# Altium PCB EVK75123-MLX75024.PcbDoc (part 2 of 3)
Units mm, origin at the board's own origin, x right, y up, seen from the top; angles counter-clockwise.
Board outline 80 x 50 mm, 8 copper layers (Top Layer, GND_T, Signal Layer 1, Vcc1, Vcc2, Signal Layer 2, GND_B, Bottom Layer), stack 1.548 mm thick; 222 components, 135 nets, 746 pads, 778 vias.
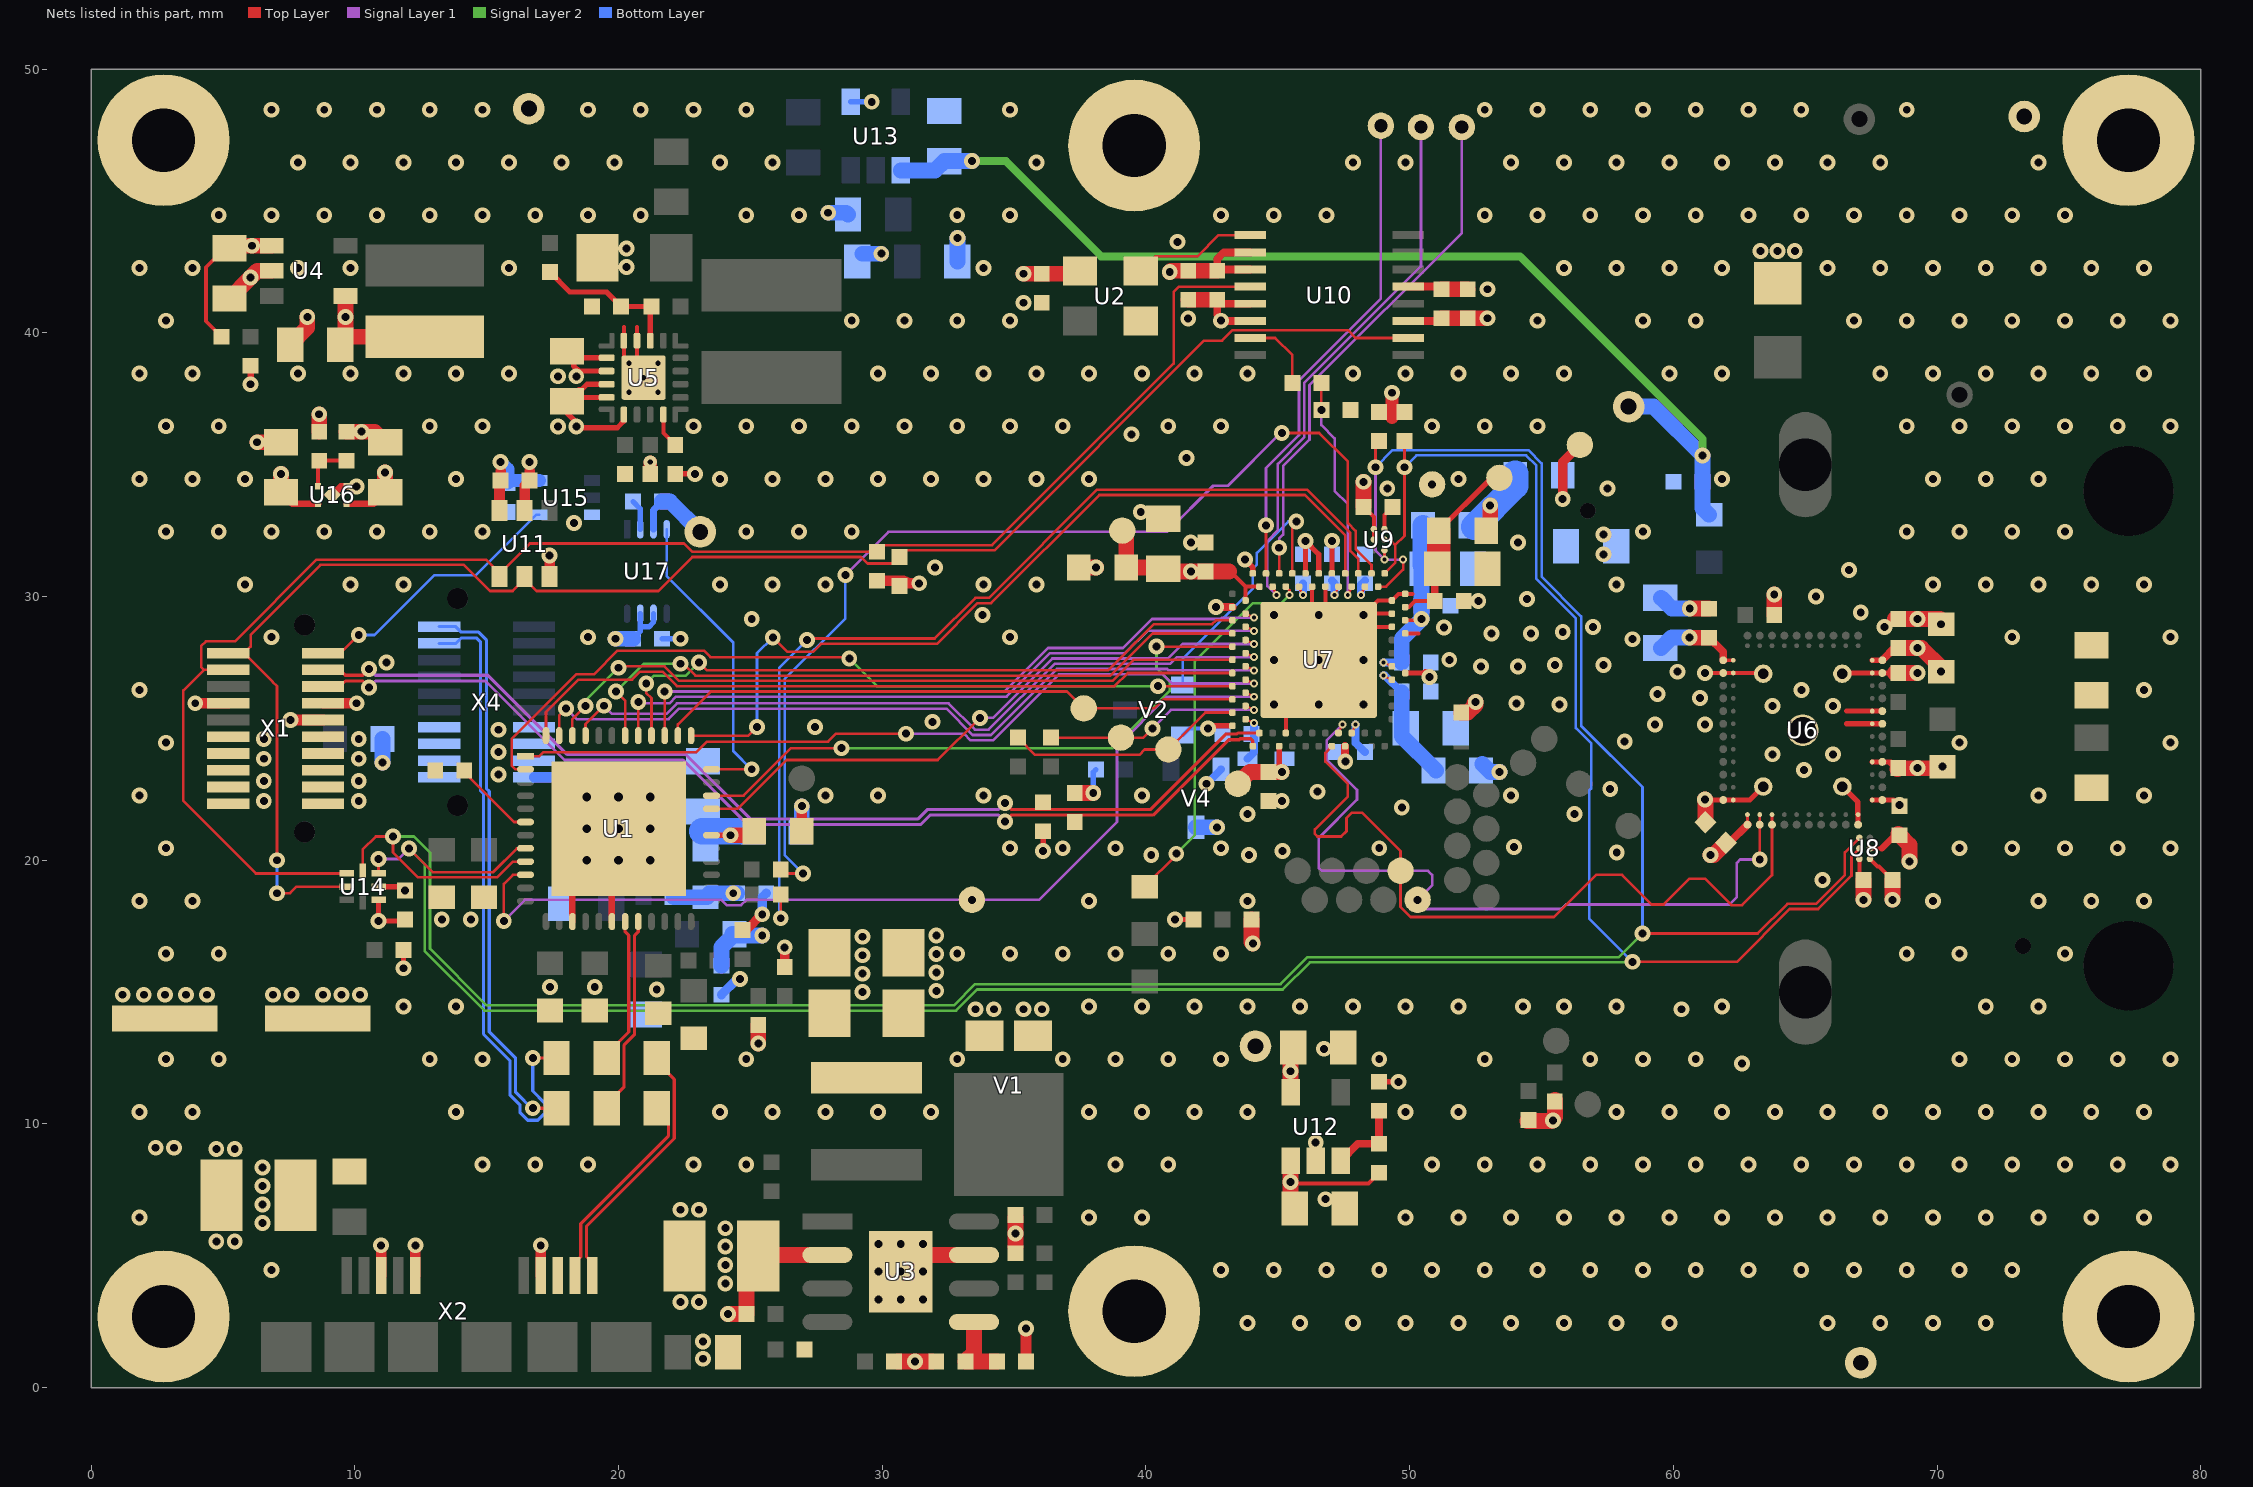
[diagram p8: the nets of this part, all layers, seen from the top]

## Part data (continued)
U10: library part ab1d2fae-9ac6-4ea7-8deb-ee514b9f58bf, "Serial programmable clock generator", Manufacturer=Cypress, Supplier Part Number 1=428-2177-5-ND
U11: library part CE87B2AE-2F79-437B-9DBA-CA9484908A67, "12-Bit Digital-to-Analog Converter with EEPROM Memory", Manufacturer=Microchip, Supplier Part Number 1=MCP4725A2T-E/CHCT-ND
U12: library part 000e727f-cc4e-40e8-9f49-f72307949e4f, "3.3V Fixed, 150 mA, Low Quiescent Current, CMOS Linear Regulator", Manufacturer="Analog Devices", Supplier Part Number 1=2074869
U13: library part 4dc81be8-c4c1-4461-86d3-06e5047a3865, "Switched-Capacitor Voltage Inverters", Manufacturer="TEXAS INSTRUMENTS", Supplier Part Number 1=595-TPS60400QDBVRQ1
U14: library part c6ef2881-e2fc-40f5-a959-5641457b75ea, "DUAL BIDIRECTIONAL I2C BUS AND SMBus VOLTAGE-LEVEL TRANSLATOR", Manufacturer="ON Semiconductor", Supplier Part Number 1=863-PCA9306AMUTCG
U15: library part FD5746C1-CD80-4158-946D-D65AE2EC754E, "74LVC1G17", Manufacturer="Texas Instruments", Supplier Part Number 1=1287609
U16: library part 41ab4844-91b0-416b-8011-5a243bc6cd3e, "1.8V LDO Regulator", Manufacturer=Micrel, Supplier Part Number 1=998-MIC5504-1.8YMTTZ
U17: library part 10037a6d-1755-4ddc-8842-5c10ed512f06, "Dual Bidirectional Voltage level translator", Manufacturer="Texas Instruments", Supplier Part Number 1=2295723
V1: library part a2494603-b754-4332-b2d6-676b3f1482f6, "12A, 100V Ultra-Low Vf Schottky Rectifier", Manufacturer=Fairchild, Supplier Part Number 1=512-FSV12100V
V2: library part 03C5F5B7-A326-4CDC-AFAF-8F2D2E9943FF, "BSS138", Manufacturer=Infineon, Supplier Part Number 1=1156434
V3: library part FC861B13-3265-48F1-9078-83CD9385FA64, "PMEG2010AEB", Manufacturer=NXP, Supplier Part Number 1=8737878
V4: library part 5BB558C5-1CEB-4DBB-9635-955197B79569, "IRLML6401PBF", Manufacturer="International Rectifier", Supplier Part Number 1=8660093
X1 X4: library part 379f8e5c-a288-4eeb-8f71-ca0e0501eadd, "High speed hermaphrodotoc strip", Manufacturer=Samtec, Supplier Part Number 1=SAM13202CT-ND
X2: library part 1b5fc05e-92d5-48fd-8827-3329ad07d580, "Micro USB 3.0 SMD horizontal", Manufacturer="Würth Electronic", Supplier Part Number 1="692 622 030 100"

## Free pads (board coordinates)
  round 0.3 smd paste-0.2 mask+0: 0(61.886,22.284) 0(61.886,22.766) 0(61.886,23.248) 0(61.886,23.729) 0(61.886,24.211) 0(61.886,24.693) 0(61.886,25.174) 0(61.886,25.656) 0(61.886,26.138) 0(61.886,26.62) 0(61.886,27.101) 0(61.886,27.583) 0(62.805,21.35) 0(62.805,28.517) 0(63.271,21.35) 0(63.271,28.517) 0(63.737,21.35) 0(63.737,28.517) 0(64.203,21.35) 0(64.203,28.517) 0(64.669,21.35) 0(64.669,28.517) 0(65.135,21.35) 0(65.135,28.517) 0(65.601,21.35) 0(65.601,28.517) 0(66.067,21.35) 0(66.067,28.517) 0(66.534,21.35) 0(66.534,28.517) 0(67,21.35) 0(67,28.517) 0(67.919,22.284) 0(67.919,22.766) 0(67.919,23.248) 0(67.919,23.729) 0(67.919,24.211) 0(67.919,24.693) 0(67.919,25.174) 0(67.919,25.656) 0(67.919,26.138) 0(67.919,26.62) 0(67.919,27.101) 0(67.919,27.583)
  round 3.4 hole 3.4 unplated: H1(77.25,34) H2(77.25,16)

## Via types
v1: diameter 0.6, hole 0.3, Top Layer to Bottom Layer, tented both sides, 705 vias
v2: diameter 0.3, hole 0.15, Top Layer to Bottom Layer, tented both sides, 49 vias
v3: diameter 0.6, hole 0.3, Top Layer to Bottom Layer, 9 vias
v4: diameter 0.7, hole 0.33, Top Layer to Bottom Layer, 9 vias
v5: diameter 0.5, hole 0.2, Top Layer to Bottom Layer, tented both sides, 6 vias

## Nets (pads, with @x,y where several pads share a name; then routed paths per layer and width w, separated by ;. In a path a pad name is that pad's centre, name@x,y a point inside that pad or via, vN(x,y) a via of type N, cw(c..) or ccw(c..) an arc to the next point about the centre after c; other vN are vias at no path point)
1V8: 1V8.1 C1.2 C6.2 C15.1 C26.2 C44.2 C86.1 L1.2 L6.1 L7.1 L8.1 L10.2 R1.2 R2.2 R11.1 R12.1 R20.1 U8.A1 U9.A1 U9.B1 U14.2 U16.1 U17.3 | length 20
  Top Layer w0.15: C1.2@48.25,33.4 48.642,33.008 U9.A1@48.642,32.557 U9.B1@48.642,32.157 ; U8.A1@67.45,20.05 67.737,19.763 67.787,19.763 C6.2@68.3,19.25
  Top Layer w0.2: U14.2@10.9,19 11.75,19 v1(11.9,18.85)
  Top Layer w0.25: v1(6.05,38.05) R20.1@6.05,38.75 ; U16.1@9.69,33.525 10.725,33.525 C26.2@11.15,33.95
  Top Layer w0.5: 49.325,36.8 v1(49.325,37.725)
  Top Layer w0.6: C26.2@11.15,33.95 v1(11.15,34.7) ; v1(25.3,13.05) R1.2@25.3,13.75 ; L6.1@37.45,31.1 v1(38.1,31.1) ; C1.2@48.244,33.406 48.25,33.412 v1(48.25,34.35) ; L8.1@52.9,32.5 53.05,32.65 v1(53.05,33.45) ; v1(68.3,18.5) C6.2@68.3,19.25
  Bottom Layer w0.25: U17.3@21.325,32.55 21.325,33.275 C15.1@21.65,33.6
  Bottom Layer w0.6: C15.1@21.65,33.6 21.95,33.6 1V8.1@23.1,32.45 ; R2.2@22.1,18.6 L10.2@23.3,18.6 ; L10.2@23.35,18.6 L10.2@23.3,18.6 ; C86.1@24.5,18.75 v1(24.35,18.75) 23.45,18.75 L10.2@23.3,18.6
  Bottom Layer w1: L1.2@52.45,32.65 54,34.2 L7.1@54,34.6 L7.1@54,34.65
1V8A: 1V8A.1 C12.2 C48.2 L7.2 U7.B14 | length 3.3
  Top Layer w0.1: v2(47.15,30.05) U7.B14@47.3,30.375
  Top Layer w0.35: v1(55.8,33.7) 55.8,35.1 1V8A.1@56.45,35.75
  Bottom Layer w0.3: C48.2@47.05,30.6 47.15,30.5 v2(47.15,30.05)
1V8ADC: 1V8ADC.1 C47.2 C63.2 C91.2 L1.1 U7.A9 U7.B5 | length 7.1
  Top Layer w0.1: v2(49,27.5) U7.B5@49.325,27.35
  Top Layer w0.15: U7.A9@49.825,29.1 v1@50.4,29.1
  Top Layer w0.3: v1@50.4,29.1 v1@50.45,29.05
  Bottom Layer w0.3: v2(49,27.5) C47.2@49.7,27.5
  Bottom Layer w0.6: C47.2@49.7,27.5 49.7,28.4 v1(50.45,29.15) 50.45,31 C91.2@50.5,31.05
  Bottom Layer w0.8: C91.2@50.5,31.2 L1.1@50.5,32.7
  other v1: 50.85,34.25
1V8ADCS: 1V8ADCS.1 C45.2 C49.2 L8.2 U7.A10 | length 7.1
  Top Layer w0.15: U7.A10@49.825,29.6 49.975,29.6 50.2,29.825 C45.2@50.95,29.825
  Top Layer w0.2: L8.2@51.1,32.5 53,34.4 53.293,34.4 53.393,34.5 1V8ADCS.1@53.4,34.5
  Top Layer w0.3: C45.2@50.95,29.825 50.95,30.925 C49.2@51.075,31.05
  Top Layer w0.9: C49.2@51.075,31.05 51.1,31.075 L8.2@51.1,32.5
1V8D: 1V8D.1 C2.1 C53.2 C59.2 C62.2 L6.2 U7.B12 U7.B20 U7.B21 U7.B30 V3.1 | length 10.1
  Top Layer w0.1: U7.B30@43.775,25.35 v2(44.1,25.2) ; v2(48.15,30.05) U7.B12@48.3,30.375
  Top Layer w0.15: 43.2,30.95 43.775,30.375 ; U7.B21@43.775,29.85 43.775,30.375 ; U7.B20@44.3,30.375 43.775,30.375
  Top Layer w0.6: 1V8D.1@39.1,32.5 39.25,32.35 L6.2@39.25,31.1 40.65,31.1 40.8,30.95 C62.2@42.25,30.95 43.15,30.95
  Bottom Layer w0.3: V3.1@43.85,23.85 44.1,24.1 v2(44.1,25.2) ; v2(48.15,30.05) 48.15,30.45 C2.1@48.3,30.6
  other v1: 41.7,30.95
1V8IO: C22.1 C81.2 C83.2 L10.1 U1.30 | length 3.4
  Top Layer w0.2: U1.30@23.575,20.95 v1(24.25,20.95)
  Top Layer w0.6: v1(24.25,20.95) 24.95,20.95 C83.2@25.1,21.1
  Bottom Layer w1: 23.175,21.1 C22.1@24.95,21.1
3V3: 3V3.1 C9.1 C11.2 C25.2 C29.2 C32.2 C33.2 C39.2 C42.2 C52.2 C54.1 C55.2 C57.2 C64.2 C66.2 C74.2 C87.1 C90.1 L2.2 L9.1 L17.1 pad.0@62.805,21.35 pad.0@67.919,22.284 pad.0@67.919,27.583 R6.1 R13.1 R14.2 R19.1 R27.2 R28.2 R34.2 R35.2 R38.2 U2.4 U4.4 U6.23 U6.33 U6.44 U7.B17 U10.2 U10.3 U10.11 U11.3 U15.5 U16.4 U17.6 U17.7 V4.2 | length 43
  Top Layer w0.1: U7.B17@45.8,30.375 v2(45.95,30.05) ; pad.0@62.805,21.35 U6.23@62.805,21.733
  Top Layer w0.2: v1(11.844,15.904) R19.1@11.844,16.594 ; U6.33@67.536,22.284 pad.0@67.919,22.284 68.341,22.284 C11.2@68.525,22.1 ; U6.44@67.536,27.583 67.866,27.583 pad.0@67.893,27.609
  Top Layer w0.25: C25.2@7.2,33.95 7.625,33.525 U16.4@8.61,33.525
  Top Layer w0.3: U10.3@43.95,42.4 42.75,42.4 C66.2@42.7,42.35 42.7,42.8 42.95,43.05 U10.2@43.95,43.05 ; U10.11@49.95,40.45 51.1,40.45 C64.2@51.2,40.55 ; C32.2@61.989,20.661 62.116,20.661 pad.0@62.805,21.35 ; pad.0@67.919,27.583 C42.2@68.4,28.064 ; C42.2@68.4,27.998 68.4,28.05 C42.2@68.525,28.05 ; C11.2@68.457,22.218 v1(68.575,22.1)
  Top Layer w0.4: U11.3@15.487,33.258 15.487,34.357 C74.2@15.53,34.4 15.53,34.75 ; R35.2@29.8,30.6 R28.2@30.8,30.6 ; R28.2@30.9,30.55 30.95,30.5 v1(31.4,30.5)
  Top Layer w0.5: R27.2@21.2,34.65 v5(21.2,35.1)
  Top Layer w0.6: C25.2@7.2,33.95 v1(7.2,34.65) ; R13.1@8.65,36.25 v1(8.65,36.91) ; C39.2@9.45,39.55 C39.2@9.65,39.75 ; v1(9.65,40.6) C39.2@9.65,39.75 ; U4.4@9.65,41.4 C39.2@9.65,39.75 ; L2.2@12.65,39.85 9.75,39.85 C39.2@9.65,39.75 ; v1(35.35,42.238) C54.1@36.05,42.238 37.4,42.238 U2.4@37.5,42.338 ; R34.2@37.3,22.55 v1(38,22.55) ; v1(40.9,42.3) 40.95,42.35 C55.2@41.6,42.35 C66.2@42.7,42.35 ; R6.1@44,17.75 44,16.9 v1(44.05,16.85) ; C64.2@51.2,40.55 C57.2@52.2,40.55 v1@52.9,40.55 ; v1(61.4,20.2) 61.528,20.2 C32.2@61.989,20.661 ; C42.2@68.525,28.05 v1(69.25,28.05) 69.4,28.05 C90.1@70.15,27.3
  Bottom Layer w0.2: C33.2@20.55,28.4 20.825,28.675 20.825,28.85 ; U17.7@20.825,29.35 20.825,28.85 ; U17.6@21.325,29.35 21.325,29.025 21.15,28.85 20.825,28.85 ; v1(38,22.55) 38,23.339 R14.2@38.1,23.439
  Bottom Layer w0.3: v1(42.3,22.9) V4.2@42.85,23.45 ; v2(45.95,30.05) C52.2@45.95,30.5
  Bottom Layer w0.5: v1(15.53,35.1) 15.8,34.83 C9.1@15.8,34.3 15.9,34.4 U15.5@17,34.4
  Bottom Layer w0.6: v1(11.05,23.7) L17.1@11.05,24.6 ; v1(19.881,28.4) C33.2@20.55,28.4 ; C87.1@23.9,16 23.9,16.7 L9.1@24.4,17.2 ; L9.1@24.31,17.2 L9.1@24.4,17.2 ; v1(25.45,17.15) 24.45,17.15 L9.1@24.4,17.2 ; R38.2@32.85,42.7 v1(32.85,43.6)
  other v1: 70.15,27.15 52.95,40.55
3V3A: 3V3A.1 C19.2 C30.2 C31.2 L12.2 pad.0@61.886,27.583 U6.11 U12.5 | length 6.6
  Top Layer w0.15: pad.0@61.886,27.583 U6.11@62.268,27.583
  Top Layer w0.3: C31.2@61.351,28.437 61.886,27.903 pad.0@61.886,27.583
  Top Layer w0.6: U12.5@45.483,11.2 45.483,12.8 v1(45.483,12) ; v1@60.616,28.437 C31.2@61.351,28.437
  Bottom Layer w0.6: L12.2@52.75,23.65 53.05,23.35 v1(53.4,23.35) ; C30.2@59.532,28.05 59.932,28.45 v1(60.603,28.45) v1@60.629,28.45
3V3A_CC: C46.2 C75.2 L12.1 U7.B4 | length 4.8
  Top Layer w0.1: v2(49,27) U7.B4@49.325,26.85
  Bottom Layer w0.3: v2(49,27) 49.066,27 49.7,26.366 C46.2@49.7,26.355
  Bottom Layer w0.6: C46.2@49.7,26.355 49.7,24.705 L12.1@51,23.405
3V3CC: 3V3CC.1 C50.1 C51.1 U7.A36 U7.B38 V3.2 V4.3 | length 5.2
  Top Layer w0.1: U7.B38@47.8,24.825 v2(47.95,25.15)
  Top Layer w0.2: v1@45.05,23.35 U7.A36@45.05,24.325
  Top Layer w0.6: 3V3CC.1@43.482,22.9 43.932,23.35 C51.1@44.65,23.35 45.05,23.35 v1(45.15,23.35)
  Bottom Layer w0.3: v2(47.95,25.15) 47.95,24.45 C50.1@48.3,24.1
  Bottom Layer w0.6: V4.3@41.9,21.25 v1(42.698,21.25)
5V0: C10.2 C20.2 C28.2 C68.2 C69.2 L3.2 R7.2 R10.1 R16.1 R37.2 R51.2 U4.1 U5.7 U5.8 U5.9 U12.1 X1.12 | length 21.2
  Top Layer w0.15: R16.1@4.95,39.85 4.35,40.45 4.35,42.474 C20.2@5.176,43.3 ; v1(45.483,7.8) 45.533,7.75 48.433,7.75 R10.1@48.833,8.15
  Top Layer w0.2: U5.8@19.55,37.55 C28.2@18.2,37.55 ; U5.7@19.55,38.05 18.807,38.05 18.607,37.85 18.5,37.85 C28.2@18.2,37.55 ; U5.9@20.2,36.9 20.2,36.65 19.95,36.4 18.614,36.4 18.05,36.964 C28.2@18.05,37.4 C28.2@18.2,37.55 ; R51.2@22.15,34.65 v1(22.9,34.65)
  Top Layer w0.4: v1(7.568,25.318) X1.12@8.8,25.318 ; R7.2@35.45,1 v1(35.45,2.25)
  Top Layer w0.6: C20.2@5.176,43.3 v1(6.1,43.3) U4.1@6.85,43.3 ; C10.2@45.483,6.95 v1(45.483,7.8) U12.1@45.483,8.6
  Signal Layer 2 w0.4: v1@29.243,14.993 v1(29.25,15)
  Bottom Layer w0.6: R37.2@29.25,43 v1(29.965,43)
  other v1: 29.25,15.7 29.25,16.4 29.25,17.1 17.7,36.45 18.4,36.45
20MHZ: U2.3 U10.1 | length 4.8
  Top Layer w0.1: U2.3@39.9,42.338 U2.3@39.8,42.338 40.362,42.9 41.95,42.9 42.75,43.7 U10.1@43.95,43.7
24V: C13.2 C17.1 C60.2 L14.1 R32.2 U3.2 X1.2 X1.4 X1.6 X1.8 X1.10 X4.2 X4.4 X4.6 X4.8 | length 5.7
  Top Layer w0.6: v1(24.15,2.8) R32.2@24.85,2.8 24.85,4.55 C60.2@25.3,5 ; C60.2@25.335,5.035 U3.2@27.92,5.035
  other v1: 24.05,3.95 24.05,4.65 24.05,5.35 24.05,6.05 6.5,6.25 6.5,6.95 6.5,7.65 6.5,8.35 6.9,14.9 7.6,14.9 8.8,14.9 9.5,14.9 10.2,14.9 10.15,22.25 10.15,23 10.15,23.85 10.15,24.6
ABIAS: ABIAS.1 C43.1 C56.2 R3.2 U13.1 | length 41.5
  Signal Layer 2 w0.3: v1(33.4,46.508) 34.692,46.508 38.3,42.9 54.179,42.9 61.1,35.979 v1(61.1,35.35)
  Bottom Layer w0.6: U13.1@30.7,46.158 32,46.158 C43.1@32.35,46.508 v1(33.4,46.508) ; ABIAS.1@58.3,37.2 59.25,37.2 v1(61.1,35.35) C56.2@61.1,34.35 61.1,33.35 R3.2@61.35,33.1
CCCLK: R15.1 R21.2 U7.B13 | length 8.8
  Top Layer w0.1: v1(46.65,37.075) R15.1@46.65,38.1 ; v2(47.65,30.05) U7.B13@47.8,30.375
  Signal Layer 1 w0.1: v1(46.65,37.075) 46.65,36.5 47.15,36 47.15,34 47.65,33.5 v2(47.65,30.05)
CSI.D0: U1.2 U7.A30 | length 30.9
  Top Layer w0.1: U1.2@16.475,23.45 16.1,23.45 15.95,23.6 15.95,24.606 18.394,27.05 19.068,27.05 19.968,27.95 23.236,27.95 23.486,27.7 28.7,27.7 v1(28.75,27.65) ; v1(40.45,26.6) U7.A30@43.275,26.6
  Signal Layer 2 w0.1: v1(28.75,27.65) 29.8,26.6 v1(40.45,26.6)
CSI.D1: U1.1 U7.B27 | length 29.6
  Top Layer w0.1: U1.1@16.475,23.95 17,23.95 17.15,24.1 22.95,24.1 23.35,24.5 27.95,24.5 28.25,24.8 v1(30.9,24.8) ; U7.B27@43.775,26.85 v2(44.1,26.7)
  Signal Layer 1 w0.1: v1(30.9,24.8) 33.098,24.8 33.348,24.55 34.2,24.55 36.7,27.05 40.636,27.05 40.986,26.7 v2(44.1,26.7)
CSI.D2: U1.48 U7.A29 | length 28
  Top Layer w0.1: U1.48@17.25,24.725 17.25,25.623 18.477,26.85 20.514,26.85 20.814,27.15 21.667,27.15 22.217,26.6 38.811,26.6 39.311,27.1 U7.A29@43.275,27.1
CSI.D3: U1.47 U7.B26 | length 29.4
  Top Layer w0.1: U1.47@17.75,24.725 17.75,25.486 v1(18.014,25.75) ; U7.B26@43.775,27.35 v2(44.1,27.2)
  Signal Layer 1 w0.1: v1(18.014,25.75) 18.414,25.35 21.902,25.35 22.302,25.75 32.431,25.75 33.431,24.75 34.117,24.75 36.617,27.25 40.8,27.25 40.85,27.2 v2(44.1,27.2)
CSI.D4: U1.46 U7.A28 | length 27.2
  Top Layer w0.1: U1.46@18.25,24.725 18.25,25.35 v1(18.75,25.85) ; v1(20,27.3) 20.05,27.35 21.75,27.35 22.3,26.8 38.728,26.8 39.528,27.6 U7.A28@43.275,27.6
  Signal Layer 2 w0.1: v1(18.75,25.85) 18.75,26.05 v1(20,27.3)
CSI.D5: U1.45 U7.B25 | length 28.3
  Top Layer w0.1: U1.45@18.75,24.725 18.75,25.16 v1(19.45,25.86) ; U7.B25@43.775,27.85 v2(44.1,27.7)
  Signal Layer 1 w0.1: v1(19.45,25.86) 19.76,25.55 21.819,25.55 22.219,25.95 32.514,25.95 33.514,24.95 34.034,24.95 36.534,27.45 40.919,27.45 41.169,27.7 v2(44.1,27.7)
CSI.D6: U1.33 U7.A27 | length 23.8
  Top Layer w0.1: U1.33@23.525,22.45 24.736,22.45 26.536,24.25 v1(28.45,24.25) ; v1(40.4,28.1) U7.A27@43.275,28.1
  Signal Layer 2 w0.1: v1(28.45,24.25) 38.736,24.25 40.9,26.414 40.9,26.786 40.4,27.286 v1(40.4,28.1)
CSI.D7: U1.32 U7.B24 | length 23.5
  Top Layer w0.1: U1.32@23.525,21.95 24.519,21.95 26.369,23.8 32.1,23.8 v1(33.7,25.4) ; U7.B24@43.775,28.35 v2(44.1,28.2)
  Signal Layer 1 w0.1: v1(33.7,25.4) 34.201,25.4 36.451,27.65 40.836,27.65 41.386,28.2 v2(44.1,28.2)
CSI.D8: U1.42 U7.A26 | length 26.5
  Top Layer w0.1: v1(19.9,26.4) 20.25,26.05 U1.42@20.25,24.725 ; v1(22.35,27.45) 22.464,27.45 22.914,27 38.645,27 40.245,28.6 U7.A26@43.275,28.6
  Signal Layer 2 w0.1: v1(19.9,26.4) 20.95,27.45 v1(22.35,27.45)
CSI.D9: U1.41 U7.B23 | length 26.1
  Top Layer w0.1: U1.41@20.75,24.725 v1(20.75,26) ; U7.B23@43.775,28.85 v2(44.1,28.7)
  Signal Layer 1 w0.1: v1(20.75,26) 20.8,25.95 21.936,25.95 22.186,26.2 34.719,26.2 36.369,27.85 39.212,27.85 40.062,28.7 v2(44.1,28.7)
CSI.D10: U1.40 U7.A25 | length 25.5
  Top Layer w0.1: v1(21.05,26.7) 21.05,26.35 21.25,26.15 U1.40@21.25,24.725 ; v1(23.05,27.5) 23.35,27.2 38.562,27.2 40.312,28.95 42.5,28.95 42.65,29.1 U7.A25@43.275,29.1
  Signal Layer 2 w0.1: v1(21.05,26.7) 21.35,27 22.55,27 v1(23.05,27.5)
CSI.D11: U1.39 U7.B22 | length 25.5
  Top Layer w0.1: U1.39@21.75,24.725 v1(21.75,26.4) ; U7.B22@43.775,29.35 v2(44.1,29.2)
  Signal Layer 1 w0.1: v1(21.75,26.4) 34.636,26.4 36.286,28.05 39.129,28.05 40.229,29.15 42.836,29.15 42.886,29.2 v2(44.1,29.2)
CSI.FSYNC: FS.1 U1.38 U7.A31 | length 22.4
  Top Layer w0.1: U1.38@22.25,24.725 22.25,25.15 23.5,26.4 37,26.4 FS.1@37.641,25.759 40.309,25.759 40.65,26.1 U7.A31@43.275,26.1
CSI.HSYNC: HS.1 R44.1 U7.B29 | length 8.5
  Top Layer w0.1: R44.1@36.4,24.65 HS.1@39.05,24.65 39.9,24.65 v1(40.25,25) ; U7.B29@43.775,25.85 v2(44.1,25.7)
  Signal Layer 1 w0.1: v1(40.25,25) 40.95,25.7 v2(44.1,25.7)
CSI.nRESET: R41.1 U7.A14 | length 37
  Top Layer w0.1: v1(26.15,17.8) R41.1@26.15,18.5 ; v1(27.15,28.35) 27.208,28.408 31.989,28.408 33.531,29.95 34.047,29.95 38.147,34.05 46.107,34.05 47.75,32.407 47.75,31.719 48.05,31.419 U7.A14@48.05,30.875
  Bottom Layer w0.1: v1(26.15,17.8) 26.1,17.85 26.1,27.3 v1(27.15,28.35)
CSI.PCLK: PCLK.1 U1.10 U7.B28 | length 36.5
  Top Layer w0.1: v1(15.65,17.7) 15.65,19.104 15.996,19.45 U1.10@16.475,19.45 ; U7.B28@43.775,26.35 v2(44.1,26.2)
  Signal Layer 1 w0.1: v1(15.65,17.7) 16.45,18.5 23.9,18.5 24.1,18.3 24.65,18.3 24.85,18.5 v1(33.4,18.5) 35.95,18.5 38.9,21.45 38.9,24.3 40.8,26.2 v2(44.1,26.2)
CSI.QUIET: U1.37 U7.A15 | length 32.8
  Top Layer w0.1: U1.37@22.75,24.725 24.925,24.725 v1(25.25,25.05) ; v1(25.85,28.45) 26.4,27.9 27.366,27.9 27.674,28.208 32.072,28.208 33.614,29.75 34.13,29.75 38.23,33.85 46.024,33.85 47.55,32.324 U7.A15@47.55,30.875
  Bottom Layer w0.1: v1(25.25,25.05) 25.25,27.85 v1(25.85,28.45)
CSI.TRIGGER: R42.1 U7.A13 | length 39.7
  Top Layer w0.1: R42.1@26.15,19.5 v1(27,19.5) ; v1(45.15,36.2) 46.566,36.2 47.65,35.116 47.65,32.79 47.95,32.49 47.95,31.802 48.55,31.202 U7.A13@48.55,30.875
  Signal Layer 1 w0.1: v1(28.6,30.814) 30.236,32.45 40.8,32.45 42.55,34.2 43.1,34.2 45.1,36.2 v1(45.15,36.2)
  Bottom Layer w0.1: v1(27,19.5) 26.3,20.2 26.3,26.864 28.6,29.164 v1(28.6,30.814)
CSI.VSYNC: R45.1 U7.A32 VS.1 | length 9.1
  Top Layer w0.1: R45.1@35.15,24.65 35.8,24 39.75,24 39.95,24.2 VS.1@40.85,24.2 42.25,25.6 U7.A32@43.275,25.6
D_B2B_N: C72.1 X4.18 | length 24.5
  Top Layer w0.12: v1(16.75,12.5) C72.1@17.65,12.5
  Bottom Layer w0.12: X4.18@13.2,28.222 13.837,28.222 14.045,28.43 14.605,28.43 14.77,28.265 14.77,22.63 14.88,22.52 14.88,13.408 15.88,12.408 15.88,11.109 16.26,10.729 16.26,10.439 16.559,10.14 16.941,10.14 17.21,10.409 17.21,10.791 16.75,11.251 v1(16.75,12.5)
D_B2B_P: C73.1 X4.20 | length 21.5
  Top Layer w0.12: v1(16.75,10.6) C73.1@17.65,10.6
  Bottom Layer w0.12: X4.20@13.2,28.857 13.828,28.857 14.035,28.65 14.696,28.65 14.99,28.356 14.99,22.721 15.1,22.611 15.1,13.499 16.1,12.499 16.1,11.2 16.75,10.55 v1(16.75,10.6)
D_USB_N: C27.2 X2.10 | length 10
  Top Layer w0.12: X2.10@19,4.25 19,4.75 18.785,4.965 18.785,6.124 22.11,9.449 22.11,11.69 21.45,12.35 C27.2@21.45,12.5
D_USB_P: C8.2 X2.9 | length 8
  Top Layer w0.12: X2.9@18.35,4.25 18.35,4.75 18.565,4.965 18.565,6.215 21.89,9.54 21.89,10.01 21.45,10.45 C8.2@21.45,10.6
DOUT_N: C27.1 C72.2 U1.19 | length 5.6
  Top Layer w0.12: C72.2@19.55,12.5 19.55,12.65 20.39,13.49 20.39,17.15 20.25,17.29 U1.19@20.25,17.675
DOUT_P: C8.1 C73.2 U1.20 | length 7.6
  Top Layer w0.12: C73.2@19.55,10.6 19.55,10.75 20.21,11.41 20.21,12.999 20.61,13.399 20.61,17.15 20.75,17.29 U1.20@20.75,17.675
EN1V5: R51.1 U5.12 | length 1.3
  Top Layer w0.15: U5.12@21.7,36.9 21.7,36.2 R51.1@22.15,35.75
EN1V8: C24.1 R13.2 U16.3 | length 2
  Top Layer w0.15: U16.3@8.61,34.175 8.61,35.11 R13.2@8.65,35.15 C24.1@9.69,35.15
EN3V3: C92.1 R10.2 U12.3 | length 3
  Top Layer w0.3: U12.3@47.383,8.6 48.033,9.25 R10.2@48.833,9.25 C92.1@48.833,10.5
FB5V: R7.1 R30.1 U3.5 | length 2.8
  Top Layer w0.6: U3.5@33.48,2.495 33.48,1.33 R30.1@33.15,1 R7.1@34.35,1
FBMIX: R9.1 R25.1 R26.2 U5.2 | length 5.7
  Top Layer w0.2: R9.1@17.4,42.3 18.15,41.55 19.55,41.55 R26.2@20.1,41 R25.1@21.25,41 21.2,40.95 U5.2@21.2,39.7
GND: C1.1 C2.2 C3.2 C5.1 C6.1 C7.1 C9.2 C10.1 C11.1 C12.1 C13.1 C15.2 C16.1 C17.2 C18.1 C19.1 C20.1 C21.1 C22.2 C23.1 C24.2 C25.1 C26.1 C28.1 C29.1 C30.1 C31.1 C32.1 C33.1 C34.1 C35.1 C36.1 C37.1 C38.1 C39.1 C40.1 C42.1 C43.2 C44.1 C45.1 C46.1 C47.1 C48.1 C49.1 C50.2 C51.2 C52.1 C53.1 C54.2 C55.1 C56.1 C57.1 C59.1 C60.1 C62.1 C63.1 C64.1 C66.1 C68.1 C69.1 C70.1 C71.1 C74.1 C75.1 C77.1 C81.1 C83.1 C84.1 C85.1 C86.2 C87.2 C89.2 C90.2 C91.1 C92.2 GND1.1 GND2.1 L15.2 pad.0@61.886,22.284 pad.0@61.886,27.101 pad.0@67,21.35 pad.0@67.919,23.729 pad.0@67.919,25.174 pad.0@67.919,25.656 pad.0@67.919,27.101 R4.1 R5.1 R18.1 R21.1 R26.1 R30.2 R33.1 R36.2 R48.2 R50.1 R54.2 R55.2 R56.2 U1.0 U1.15 U1.18 U2.2 U3.0 U3.7 U4.2 U5.0 U5.3 U5.4 U5.5 U5.6 U6.0 U6.12 U6.22 U6.32 U6.36 U6.39 U6.40 U6.43 U7.0 U7.A5 U7.A8 U7.A11 U7.A16 U7.A17 U7.A18 U7.A22 U7.A24 U7.A33 U7.A41 U7.B8 U7.B9 U7.B10 U7.B15 U7.B16 U7.B33 U8.A2 U8.B1 U9.A2 U10.5 U10.6 U10.13 U11.2 U11.6 U12.2 U13.4 U14.1 U15.3 U16.0 U16.2 U17.2 V1.1 V1.3 V2.2 X1.1 X1.3 X1.5 X1.7 X1.9 X1.13 X1.14 X2.3 X2.5 X2.7 X2.8 X4.1 X4.3 X4.5 X4.7 | length 105.3
  Top Layer w0.15: 20.2,40.215 U5.4@20.2,39.7 20.2,39.05 U5.0@20.7,38.55 ; 20.7,40.215 U5.3@20.7,39.7 U5.0@20.7,38.55 ; v5(20.95,38.3) U5.0@20.7,38.55 ; U7.B33@45.3,24.825 U7.0@45.3,26.35 ; U7.0@46.3,29.4 U7.B16@46.3,30.375 ; U7.0@46.8,27.85 U7.B15@46.8,30.375 ; U7.0@47.8,28.85 U7.B8@49.325,28.85 ; U7.0@48.3,29.35 U7.B9@49.325,29.35 ; U7.0@48.35,29.4 48.8,29.85 U7.B10@49.325,29.85 49.575,30.1 U7.A11@49.825,30.1 50.112,30.1 ; U9.A2@49.042,32.557 49.042,33.092 C1.1@49.35,33.4 ; U7.A8@49.786,28.6 U7.A8@49.825,28.6 50.328,28.6 ; v1(61.2,27.1) 61.201,27.101 pad.0@61.886,27.101 U6.12@62.268,27.101 63.375,27.101 U6.0@63.402,27.074 ; C6.1@67.05,19.4 U8.A2@67.05,20.05 ; U8.B1@67.45,20.45 67.9,20.45
  Top Layer w0.2: U14.1@10.9,18.5 v1(10.9,17.7) 11.85,17.7 C44.1@11.9,17.75 ; C28.1@18.05,39.3 C28.1@18.3,39.05 ; U5.6@19.55,38.55 18.494,38.55 18.3,38.744 C28.1@18.3,39.05 ; U5.5@19.55,39.05 C28.1@18.3,39.05 ; v1(36.1,20.35) R33.1@36.1,21.1 ; v1(41.1,17.75) R55.2@41.8,17.75 ; v1@42.45,25.1 U7.A33@43.275,25.1 ; v1(43.75,31.4) 44.05,31.1 U7.A22@44.05,30.875 ; U7.A18@46.05,30.875 v1(46.05,32.1) 46.55,31.6 U7.A17@46.55,30.875 ; v3(46.55,27.6) 46.8,27.85 47.8,28.85 v3(48.25,29.3) 48.3,29.35 U7.0@48.35,29.4 ; v1(46.75,12.85) 46.8,12.9 C19.1@47.483,12.9 ; U7.A16@47.05,30.875 v1(47.05,32.112) ; C92.2@48.833,11.6 v1(49.575,11.6) ; U7.A5@49.825,27.1 v1@50.6,27.1 ; v1@61.211,22.289 61.216,22.284 pad.0@61.886,22.284 ; pad.0@61.907,22.284 U6.22@62.268,22.284 62.893,22.284 U6.0@63.402,22.794 ; U6.0@66.402,22.794 66.99,22.206 U6.32@66.99,21.733 ; U6.0@66.402,27.074 U6.0@66.441,27.035 ; U6.0@66.441,27.101 U6.43@67.536,27.101 pad.0@67.919,27.101 C36.1@68.335,27.101 ; 66.575,25.174 U6.39@67.536,25.174 pad.0@67.919,25.174 ; 66.575,25.656 U6.40@67.536,25.656 pad.0@67.919,25.656 ; pad.0@67,21.335 pad.0@67,21.35 U6.32@67,21.733 ; U6.36@67.536,23.729 pad.0@67.919,23.729 C34.1@68.237,23.729 ; C34.1@68.237,23.663 C34.1@68.45,23.45
  Top Layer w0.25: U16.0@9.15,33.85 9.475,34.175 U16.2@9.69,34.175 v1(10.065,34.175) ; U1.15@18.25,17.675 U1.0@18.25,19.45 ; U1.18@19.75,17.675 U1.0@19.75,20.95 ; C6.1@67.05,19.4 C6.1@67.2,19.25 ; 67.9,20.45 68.45,21 C11.1@68.525,21
  Top Layer w0.3: v1(41.7,32.05) C62.1@42.25,32.05 ; v1(42.65,29.6) U7.A24@43.275,29.6 ; U10.6@43.95,40.45 42.95,40.45 42.7,40.7 C66.1@42.7,41.25 42.85,41.1 U10.5@43.95,41.1 ; v1@47.55,23.8 U7.A41@47.55,24.325 ; U10.13@49.95,41.75 51.1,41.75 C64.1@51.2,41.65 ; v1@50.6,27.1 v1(50.75,26.95) ; C36.1@68.335,27.035 C36.1@68.4,27.1
  Top Layer w0.35: R50.1@24.7,17.35 24.85,17.35 24.875,17.375 24.875,17.388 25.437,17.95 v1(25.45,17.95) ; R5.1@26.3,15.95 v1(26.3,16.7) ; v1(30.7,4.4) U3.0@31.335,5.035
  Top Layer w0.4: v1(3.953,25.953) X1.13@5.2,25.953 ; X1.14@8.8,25.953 v1(10.072,25.953) ; X2.3@11,4.25 v1(11,5.4) ; X2.5@12.3,4.25 v1(12.3,5.4) ; U11.2@16.437,33.258 16.437,34.207 C74.1@16.63,34.4 16.63,34.75 ; X2.7@17.05,4.25 v1(17.05,5.4) ; U11.6@17.387,30.758 v1(17.387,31.56) ; C83.1@26.9,21.1 26.95,21.15 v1(26.95,22.05)
  Top Layer w0.6: C20.1@5.25,41.3 v1(6.05,42.1) 6.3,42.35 U4.2@6.85,42.35 ; v1(6.3,35.85) C25.1@7.2,35.85 ; C39.1@7.55,39.55 8.2,40.2 v1(8.2,40.6) ; C24.2@9.69,36.25 10.75,36.25 C26.1@11.15,35.85 ; v1(10.25,36.25) C26.1@10.75,36.25 ; R18.1@30.592,1 v1(31.242,1) R30.2@31.892,1 ; U3.0@31.335,5.035 U3.7@33.48,5.035 ; C71.1@35.05,5.35 v1(35.05,5.85) C70.1@35.05,6.45 ; C55.1@41.6,41.25 C66.1@42.7,41.25 ; C64.1@51.2,41.65 C57.1@52.2,41.65 ; R56.2@51.95,25.6 52.2,25.6 52.5,25.9 52.45,25.95 v1(52.5,26) ; R48.2@54.455,10.11 55.355,10.11 55.505,10.26 R54.2@55.505,10.91 ; v1(60.616,29.55) 61.339,29.55 C31.1@61.351,29.537 ; v1(61.2,22.3) 61.211,22.289 C32.1@61.211,21.439 ; C38.1@63.821,29.3 v1(63.821,30.071) ; v1(67.2,18.5) C6.1@67.2,19.25 ; C36.1@68.4,27.1 C36.1@68.525,27.1 v1@69.15,27.1 ; C42.1@68.4,29.15 C42.1@68.525,29.15 v1(69.25,29.15) C90.2@70.1,29.15 ; C34.1@68.5,23.45 68.54,23.49 69.96,23.49 C89.2@70,23.45 ; C11.1@68.525,21 C11.1@68.575,20.95 68.95,20.575 v1(68.95,19.95)
  Signal Layer 1 w0.4: v1(10.072,25.953) v1@10.1,25.925
  Bottom Layer w0.15: V2.2@41.4,24.75 41.65,25 v1(42.35,25)
  Bottom Layer w0.2: C15.2@20.55,33.6 20.825,33.325 U17.2@20.825,32.55 ; C33.1@21.65,28.4 v1(22.35,28.4) ; U13.4@28.8,48.758 v1(29.6,48.758)
  Bottom Layer w0.3: v1(47.05,32.112) v1@47.088,32.15
  Bottom Layer w0.35: C87.2@23.9,14.9 24.5,15.5 v1(24.6,15.5) ; v1(25.45,17.95) 25.45,18.6 C86.2@25.6,18.75
  Bottom Layer w0.4: X4.1@16.8,23.142 18.058,23.142 v4(18.8,22.4) ; v1@26.938,22.062 v1(26.95,22.05)
  Bottom Layer w0.6: C22.2@26.9,21.1 26.95,21.15 v1(26.95,22.05) ; v1(27.95,44.55) 28.635,44.55 C77.1@28.7,44.485 ; C30.1@59.532,29.95 59.945,29.537 59.958,29.55 v1(60.616,29.55)
  other v1: 23.2,1.1 23.2,1.75 43.843,2.458 45.843,2.458 47.843,2.458 49.843,2.458 51.843,2.458 53.843,2.458 55.843,2.458 57.843,2.458 59.843,2.458 65.843,2.458 67.843,2.458 69.843,2.458 71.843,2.458 22.35,3.25 23.05,3.25 29.85,3.35 30.7,3.35 31.55,3.35 29.85,4.4 31.55,4.4 6.843,4.458 42.843,4.458 44.843,4.458 46.843,4.458 48.843,4.458 50.843,4.458 52.843,4.458 54.843,4.458 56.843,4.458 58.843,4.458 60.843,4.458 62.843,4.458 64.843,4.458 66.843,4.458 68.843,4.458 70.843,4.458 72.843,4.458 29.85,5.45 30.7,5.45 31.55,5.45 4.75,5.55 5.45,5.55 1.843,6.458 37.843,6.458 39.843,6.458 49.843,6.458 51.843,6.458 53.843,6.458 55.843,6.458 57.843,6.458 59.843,6.458 61.843,6.458 63.843,6.458 65.843,6.458 67.843,6.458 69.843,6.458 71.843,6.458 73.843,6.458 75.843,6.458 77.843,6.458 22.35,6.75 23.05,6.75 46.8,7.15 14.843,8.458 16.843,8.458 18.843,8.458 22.843,8.458 24.843,8.458 38.843,8.458 40.843,8.458 50.843,8.458 52.843,8.458 54.843,8.458 56.843,8.458 58.843,8.458 60.843,8.458 62.843,8.458 64.843,8.458 66.843,8.458 68.843,8.458 70.843,8.458 72.843,8.458 74.843,8.458 76.843,8.458 78.843,8.458 4.75,9.05 5.45,9.05 2.45,9.1 3.15,9.1 46.433,9.3 55.43,10.135 1.843,10.458 3.843,10.458 13.843,10.458 23.843,10.458 25.843,10.458 27.843,10.458 29.843,10.458 31.843,10.458 37.843,10.458 39.843,10.458 41.843,10.458 43.843,10.458 49.843,10.458 51.843,10.458 57.843,10.458 59.843,10.458 61.843,10.458 63.843,10.458 65.843,10.458 67.843,10.458 69.843,10.458 71.843,10.458 73.843,10.458 75.843,10.458 77.843,10.458 62.6,12.3 2.843,12.458 4.843,12.458 12.843,12.458 14.843,12.458 24.843,12.458 32.843,12.458 36.843,12.458 38.843,12.458 40.843,12.458 42.843,12.458 48.843,12.458 52.843,12.458 56.843,12.458 58.843,12.458 60.843,12.458 70.843,12.458 72.843,12.458 74.843,12.458 76.843,12.458 78.843,12.458 33.53,14.35 34.23,14.35 35.35,14.35 36.05,14.35 60.3,14.35 11.843,14.458 13.843,14.458 37.843,14.458 39.843,14.458 41.843,14.458 43.843,14.458 45.843,14.458 47.843,14.458 49.843,14.458 51.843,14.458 54.3,14.45 55.843,14.458 57.843,14.458 61.843,14.458 71.843,14.458 73.843,14.458 1.2,14.9 2,14.9 2.8,14.9 3.6,14.9 4.4,14.9 32.05,15.05 21.45,15.1 17.4,15.2 19.1,15.2 32.05,15.75 32.05,16.45 2.843,16.458 4.843,16.458 32.843,16.458 34.843,16.458 36.843,16.458 38.843,16.458 40.843,16.458 42.843,16.458 68.843,16.458 70.843,16.458 74.843,16.458 32.05,17.15 13.3,17.75 14.4,17.75 1.843,18.458 3.843,18.458 37.843,18.458 43.843,18.458 69.843,18.458 73.843,18.458 75.843,18.458 77.843,18.458 65.65,19.25 40.2,20.2 43.9,20.2 57.85,20.3 45.175,20.35 2.843,20.458 34.843,20.458 36.843,20.458 38.843,20.458 42.843,20.458 48.843,20.458 70.843,20.458 72.843,20.458 74.843,20.458 76.843,20.458 78.843,20.458 53.95,20.5 43.85,21.75 56.25,21.75 49.7,22 6.55,22.25 45.15,22.25 1.843,22.458 27.843,22.458 29.843,22.458 33.843,22.458 39.843,22.458 53.843,22.458 73.843,22.458 77.843,22.458 46.5,22.6 57.6,22.7 6.55,23 15.45,23.25 64.954,23.417 69.25,23.5 70.2,23.55 47.557,23.75 6.55,23.85 63.754,24.017 66.05,24.017 15.45,24.1 2.843,24.458 70.843,24.458 78.843,24.458 58.15,24.5 6.55,24.6 15.45,24.95 27.45,25.05 59.3,25.15 61.2,25.15 31.9,25.25 63.754,25.85 66.05,25.85 55.675,25.9 54.05,25.95 61,26.15 59.4,26.3 1.843,26.458 64.85,26.45 77.843,26.458 69.25,27.1 60.15,27.15 52.7,27.35 54.1,27.35 55.5,27.4 57.35,27.4 11.2,27.5 51.5,27.6 58.45,28.382 6.843,28.458 18.843,28.458 34.843,28.458 72.843,28.458 78.843,28.458 53.1,28.6 54.6,28.6 55.8,28.65 51.3,28.825 56.95,28.85 68,28.85 70.15,28.95 25.05,29.15 33.8,29.3 67.1,29.4 52.6,29.825 54.45,29.9 65.4,30 5.843,30.458 9.843,30.458 11.843,30.458 23.843,30.458 25.843,30.458 27.843,30.458 33.843,30.458 35.843,30.458 57.843,30.458 69.843,30.458 71.843,30.458 73.843,30.458 75.843,30.458 77.843,30.458 66.65,31 32,31.1 57.35,31.6 54.1,32.05 57.35,32.35 2.843,32.458 4.843,32.458 6.843,32.458 8.843,32.458 10.843,32.458 12.843,32.458 14.843,32.458 24.843,32.458 26.843,32.458 28.843,32.458 58.843,32.458 68.843,32.458 70.843,32.458 72.843,32.458 74.843,32.458 18.307,32.79 39.8,33.2 49.15,34.1 57.5,34.1 1.843,34.458 3.843,34.458 5.843,34.458 13.843,34.458 23.843,34.458 25.843,34.458 27.843,34.458 29.843,34.458 31.843,34.458 33.843,34.458 35.843,34.458 37.843,34.458 51.843,34.458 61.843,34.458 69.843,34.458 71.843,34.458 73.843,34.458 16.63,35.1 41.537,35.258 39.45,36.15 2.843,36.458 4.843,36.458 12.843,36.458 14.843,36.458 22.843,36.458 24.843,36.458 26.843,36.458 28.843,36.458 30.843,36.458 32.843,36.458 34.843,36.458 36.843,36.458 40.843,36.458 42.843,36.458 50.843,36.458 52.843,36.458 54.843,36.458 68.843,36.458 70.843,36.458 72.843,36.458 74.843,36.458 76.843,36.458 78.843,36.458 17.7,38.35 18.4,38.35 1.843,38.458 3.843,38.458 7.843,38.458 9.843,38.458 11.843,38.458 13.843,38.458 15.843,38.458 29.843,38.458 31.843,38.458 33.843,38.458 35.843,38.458 37.843,38.458 39.843,38.458 41.843,38.458 43.843,38.458 47.843,38.458 49.843,38.458 51.843,38.458 53.843,38.458 55.843,38.458 59.843,38.458 61.843,38.458 67.843,38.458 69.843,38.458 71.843,38.458 73.843,38.458 75.843,38.458 77.843,38.458 2.843,40.458 28.843,40.458 30.843,40.458 32.843,40.458 34.843,40.458 42.843,40.458 54.843,40.458 58.843,40.458 60.843,40.458 66.843,40.458 68.843,40.458 70.843,40.458 72.843,40.458 74.843,40.458 76.843,40.458 78.843,40.458 41.6,40.538 35.35,41.138 52.95,41.65 1.843,42.458 3.843,42.458 7.843,42.458 9.843,42.458 15.843,42.458 33.843,42.458 55.843,42.458 57.843,42.458 59.843,42.458 61.843,42.458 65.843,42.458 67.843,42.458 69.843,42.458 71.843,42.458 73.843,42.458 75.843,42.458 77.843,42.458 20.3,42.5 63.3,43.1 63.95,43.1 64.6,43.1 20.3,43.2 41.2,43.45 4.843,44.458 6.843,44.458 8.843,44.458 10.843,44.458 12.843,44.458 14.843,44.458 16.843,44.458 18.843,44.458 20.843,44.458 24.843,44.458 26.843,44.458 32.843,44.458 34.843,44.458 42.843,44.458 44.843,44.458 46.843,44.458 52.843,44.458 54.843,44.458 56.843,44.458 58.843,44.458 60.843,44.458 62.843,44.458 64.843,44.458 66.843,44.458 68.843,44.458 70.843,44.458 72.843,44.458 74.843,44.458 7.843,46.458 9.843,46.458 11.843,46.458 13.843,46.458 15.843,46.458 17.843,46.458 19.843,46.458 23.843,46.458 25.843,46.458 35.843,46.458 47.843,46.458 49.843,46.458 53.843,46.458 55.843,46.458 57.843,46.458 59.843,46.458 61.843,46.458 63.843,46.458 65.843,46.458 67.843,46.458 73.843,46.458 6.843,48.458 8.843,48.458 10.843,48.458 12.843,48.458 14.843,48.458 18.843,48.458 20.843,48.458 22.843,48.458 24.843,48.458 34.843,48.458 52.843,48.458 54.843,48.458 56.843,48.458 58.843,48.458 60.843,48.458 62.843,48.458 64.843,48.458 68.843,48.458
  other v3: 44.85,25.9 46.55,25.9 48.25,25.9 44.85,27.6 48.25,27.6 44.85,29.3 46.55,29.3
  other v4: 18.8,20 20,20 21.2,20 18.8,21.2 20,21.2 21.2,21.2 20,22.4 21.2,22.4
  other v5: 20.4,37.75 21.5,37.75 20.4,38.85 21.5,38.85
GPO0: R17.1 U7.B18 | length 14.4
  Top Layer w0.1: R17.1@39.95,19 41.15,20.2 v1(41.15,20.25) ; U7.B18@45.3,30.375 45.446,30.229 v2(45.446,30.05)
  Signal Layer 2 w0.1: v1(41.15,20.25) 41.85,20.95 41.85,27.55 44.05,29.75 45.146,29.75 v2(45.446,30.05)
GPO1: GPO1.1 U7.A20 | length 19.8
  Top Layer w0.1: U7.A20@45.05,30.875 v1(45.05,31.85)
  Signal Layer 1 w0.1: v1(45.05,31.85) 45.05,32.2 45.2,32.35 45.2,34.95 46.2,35.95 46.2,38.017 51.975,43.792 GPO1.1@51.975,47.8
GPO2: GPO2.1 U7.B19 | length 20.7
  Top Layer w0.1: U7.B19@44.8,30.375 v2(44.95,30.05)
  Signal Layer 1 w0.1: v2(44.95,30.05) 44.6,30.4 44.6,32.114 45,32.514 45,35.033 46,36.033 46,38.1 50.425,42.525 GPO2.1@50.425,47.8
GPO3: GPO3.1 U7.A21 | length 18.8
  Top Layer w0.1: U7.A21@44.55,30.875 v1(44.55,32.7)
  Signal Layer 1 w0.1: v1(44.55,32.7) 44.55,34.866 45.8,36.116 45.8,38.2 48.907,41.307 GPO3.1@48.907,47.85
HPORB: U7.A19 V2.1 | length 10.2
  Top Layer w0.1: U7.A19@45.55,30.875 45.55,32.7 v1(45.7,32.85)
  Bottom Layer w0.1: V2.1@41.4,26.65 41.4,27.65 44.05,30.3 44.05,31.064 44.2,31.214 44.2,31.65 45.4,32.85 v1(45.7,32.85)
I2CH.SCL: R28.1 U10.10 U11.5 U14.6 X1.19 | length 64.2
  Top Layer w0.1: X1.19@5.2,27.858 5.804,27.858 X1.19@5.806,27.856 ; v1(7.05,18.75) 7.543,18.75 7.793,19 U14.6@9.7,19 ; v1(7.05,20) 7.05,26.6 6.887,26.762 6.887,26.774 X1.19@5.806,27.856 ; U11.5@16.437,30.857 U11.5@16.437,30.758 U11.5@16.437,30.663 ; U10.10@49.95,39.8 47.95,39.8 47.65,40.1 43.288,40.1 42.888,39.7 42.2,39.7 34.25,31.75 30.9,31.75 R28.1@30.65,31.5 30.4,31.25 29.438,31.25 29.188,31.5 22.8,31.5 21.508,30.208 16.892,30.208 U11.5@16.437,30.663 ; X1.19@5.806,27.856 6.05,28.1 6.05,28.55 8.7,31.2 14.133,31.2 15.125,30.208 15.988,30.208 16.437,30.657 U11.5@16.437,30.663
  Bottom Layer w0.1: v1(7.05,18.75) v1(7.05,20)
I2CH.SDA: R35.1 U10.4 U11.4 U14.5 X1.17 | length 62.3
  Top Layer w0.1: X1.17@5.2,27.223 4.277,27.223 ; U14.5@9.7,19.5 6.25,19.5 3.5,22.25 3.5,26.445 4.277,27.223 ; U11.4@15.487,30.758 U11.4@15.487,30.857 ; U10.4@43.95,41.75 41.25,41.75 41.05,41.55 41.05,38.833 34.167,31.95 30.05,31.95 R35.1@29.8,31.7 22.789,31.7 22.48,32.01 16.64,32.01 U11.4@15.487,30.857 ; 4.277,27.223 4.173,27.327 4.173,28.123 4.35,28.3 5.45,28.3 8.55,31.4 14.98,31.4 15.487,30.893 U11.4@15.487,30.857
I2CL.SCL: R11.2 U1.8 U7.A12 U8.B2 U9.B2 U14.3 | length 101
  Top Layer w0.1: U14.3@10.9,19.5 v1(10.9,20.05) ; v1(12.05,20.45) 12.95,19.55 15.25,19.55 16.15,20.45 U1.8@16.475,20.45 ; U9.B2@49.042,32.157 49.243,32.157 49.45,31.95 ; U7.A12@49.05,30.875 49.45,31.275 49.45,31.95 ; R11.2@49.8,35.9 v1(49.8,34.9) 49.8,32.3 49.45,31.95 ; v1(58.45,16.15) 62.4,16.15 64.4,18.15 65.483,18.15 66.75,19.417 66.75,20.15 U8.B2@67.05,20.45
  Signal Layer 1 w0.1: v1(10.9,20.05) 11.65,20.05 v1(12.05,20.45)
  Signal Layer 2 w0.1: v1(12.05,20.45) 12.65,19.85 12.65,16.567 14.917,14.3 32.8,14.3 33.6,15.1 45.183,15.1 46.21,16.127 58.427,16.127 v1(58.45,16.15)
  Bottom Layer w0.1: v1(49.8,34.9) 50.25,35.35 54.412,35.35 54.8,34.962 54.8,30.667 56.3,29.167 56.3,25.017 56.879,24.439 56.879,22.716 56.8,22.637 56.8,17.8 v1(58.45,16.15)
I2CL.SDA: R12.2 U1.9 U7.B11 U8.C2 U9.C2 U14.4 | length 105.5
  Top Layer w0.1: U14.4@10.3,19.6 10.3,20.403 10.797,20.9 v1(11.45,20.9) 11.45,20.3 12.4,19.35 15.4,19.35 16,19.95 U1.9@16.475,19.95 ; v1(48.7,34.9) 48.7,35.767 R12.2@48.833,35.9 ; U7.B11@48.8,30.375 49.1,30.375 49.75,31.025 v2(49.75,31.4) ; v2(49.042,31.408) U9.C2@49.042,31.757 ; v1(58.825,17.225) 63.192,17.225 64.317,18.35 65.4,18.35 66.5,19.45 66.5,20.3 U8.C2@67.05,20.85
  Signal Layer 1 w0.1: v1(48.7,34.9) 48.7,31.75 v2(49.042,31.408) 49.05,31.4 v2(49.75,31.4)
  Signal Layer 2 w0.1: v1(11.45,20.9) 12.236,20.9 12.85,20.286 12.85,16.65 15,14.5 32.717,14.5 33.517,15.3 45.1,15.3 46.127,16.327 57.927,16.327 v1(58.825,17.225)
  Bottom Layer w0.1: v1(48.7,34.9) 49.35,35.55 54.495,35.55 55,35.045 55,30.75 56.5,29.25 56.5,25.1 58.825,22.775 v1(58.825,17.225)
ID: R4.2 U1.6 | length 3.2
  Top Layer w0.1: R4.2@14.15,23.4 14.15,23.34 16.04,21.45 U1.6@16.475,21.45
LCLK1: R15.2 U10.7 | length 2.9
  Top Layer w0.1: U10.7@43.95,39.8 44.9,39.8 45.55,39.15 R15.2@45.55,38.1
LDEN: U1.35 U17.4 | length 12
  Top Layer w0.1: U1.35@23.525,23.45 v1(25.05,23.45)
  Bottom Layer w0.1: U17.4@21.825,32.55 21.825,30.775 24.35,28.25 24.35,24.15 v1(25.05,23.45)
LDENH: U15.4 X1.20 | length 10.3
  Top Layer w0.1: X1.20@8.85,27.85 9.458,27.85 v1(10.15,28.542)
  Bottom Layer w0.1: v1(10.15,28.542) 10.75,28.542 13.013,30.805 14.585,30.805 16.88,33.1 U15.4@17,33.1
LED.MOD_N: R34.1 U7.A34 X1.16 | length 39.6
  Top Layer w0.12: X1.16@8.8,26.588 9.437,26.588 9.645,26.795 10.301,26.795 v1(10.541,26.555) ; v1(34.65,21.47) 34.89,21.71 40.272,21.71 43.132,24.57 43.538,24.57 43.573,24.605 43.97,24.605 44.05,24.525 U7.A34@44.05,24.325
  Signal Layer 1 w0.12: v1(10.541,26.555) 10.781,26.795 14.955,26.795 17.95,23.8 22.45,23.8 24.9,21.35 31.449,21.35 31.809,21.71 34.41,21.71 v1(34.65,21.47)
LED.MOD_P: R33.2 U7.B31 X1.18 | length 39.6
  Top Layer w0.12: X1.18@8.8,27.223 9.427,27.223 9.635,27.015 10.301,27.015 v1(10.541,27.255) ; v1(34.65,22.17) 34.89,21.93 40.181,21.93 43.041,24.79 43.447,24.79 43.482,24.825 U7.B31@44.3,24.825
  Signal Layer 1 w0.12: v1(10.541,27.255) 10.781,27.015 15.046,27.015 18.041,24.02 22.541,24.02 24.991,21.57 31.358,21.57 31.718,21.93 34.41,21.93 v1(34.65,22.17)
MH1: MH1.1
MH2: MH2.1
MH3: MH3.1
MH4: MH4.1
MH5: MH5.1
MH6: MH6.1
MLX.COL0: COL0.1 pad.0@63.271,21.35 U6.24 U7.B37 | length 29.1
  Top Layer w0.1: U7.B37@47.3,24.825 v2(47.45,25.15) ; v1(63.271,20.029) pad.0@63.271,21.35 U6.24@63.271,21.733
  Signal Layer 1 w0.1: v2(47.45,25.15) 46.85,24.55 46.85,23.82 48,22.67 48,22.3 46.55,20.85 46.55,19.716 46.666,19.6 50.7,19.6 50.85,19.45 50.85,19.05 v1(50.3,18.5) 50.65,18.15 55.75,18.15 55.925,18.325 62.125,18.325 62.4,18.6 62.4,19.9 62.529,20.029 v1(63.271,20.029)
MLX.COL1: COL1.1 pad.0@63.737,21.35 U6.25 U7.A40 | length 29.9
  Top Layer w0.1: U7.A40@47.05,24.325 46.8,24.075 46.8,23.745 47.65,22.895 47.65,22.417 46.4,21.167 46.4,21 46.5,20.9 47.4,20.9 47.6,21.1 47.6,21.6 47.8,21.8 48.2,21.8 49.65,20.35 COL1.1@49.65,19.6 49.65,18.769 49.65,18.231 50.031,17.85 55.471,17.85 57.071,19.45 58.05,19.45 59.175,18.325 59.625,18.325 60.6,19.3 61.2,19.3 62.2,18.3 62.6,18.3 63.737,19.437 pad.0@63.737,21.35 U6.25@63.737,21.733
